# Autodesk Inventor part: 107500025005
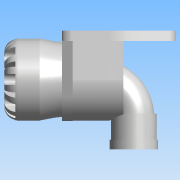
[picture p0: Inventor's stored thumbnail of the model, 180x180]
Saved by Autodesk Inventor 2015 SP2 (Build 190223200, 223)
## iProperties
Created: 2017-01
Part Number: 107500025005
Material: PVC-Piping
Description: PLASSON WALL PLATE ELBOW 25X1/2" SERIES 1
Document SubType Name: Modeling
Designer: Кирилл
Mass: 122.736 g
Surface Area: 365.546 cm^2
Volume: 87.6688 cm^3
Density: 1.4 g/cm^3
Appearance: Smooth - White
Author: KIM
Author: naamad
Title: SR1-ELBOW-BRACKET-20-CAT
Organization: PLASSON
Sending System: PRO/ENGINEER BY PARAMETRIC TECHNOLOGY CORPORATION, 2014000
Preprocessor: PRO/ENGINEER BY PARAMETRIC TECHNOLOGY CORPORATION, 2014000
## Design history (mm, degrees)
derived "1075.ipt"
feature "Solid1::1075.ipt"
feature "Solid8::1075.ipt"
feature "Solid11::1075.ipt"
tag "TaggingFeature1"
body "Solid1"
body "Solid2"
body "Solid3"
other parameters: "d3" = 25, "d4" = 47, "d5" = 31.25, "d6" = 20.16, "d7" = 48, "d9" = 41.36, "d13" = 3.96, "d14" = 7.92, "d26" = 74, "d29" = 23.47506, "d31" = 0, "d32" = 0, "d39" = 6.3, "d41" = 6.3, "d42" = 0, "d44" = 360 deg, "d46" = 8 deg, "d47" = 8 deg, "d48" = 0.5, "d49" = 0.5, "d51" = 0, "d53" = 360 deg, "d55" = 0.25, "d61" = 2.5, "d65" = 8.94247, "d69" = 90 deg, "d71" = 4.658, "d72" = 0, "d73" = 0, "d74" = 5.5, "d78" = 28, "d79" = 39, "d80" = 98, "d81" = 6, "d82" = 0, "d83" = 6, "d84" = 0, "d87" = 27, "d88" = 0, "d89" = 27, "d90" = 0, "d91" = 28, "d93" = 98, "d94" = 39, "d95" = 6, "d96" = 0, "d98" = 6, "d99" = 0, "d100" = 4.5, "d101" = 19, "d102" = 29, "d103" = 0, "d105" = 0, "d107" = 0, "d108" = 18.631, "d109" = 3.7262, "d110" = 0.74524, "d111" = 17, "d112" = 20.4, "d113" = 16.7679, "d114" = 5.66667, "d_" = 25, "Rp_" = 18.631, "E_" = 47, "l_" = 48, "l_2" = 17, "A_" = 74, "A_2" = 28, "L_" = 78, "H_" = 98, "d30" = 26.0834, "d37" = 31.25, "d38" = 47, "d40" = 7.875
